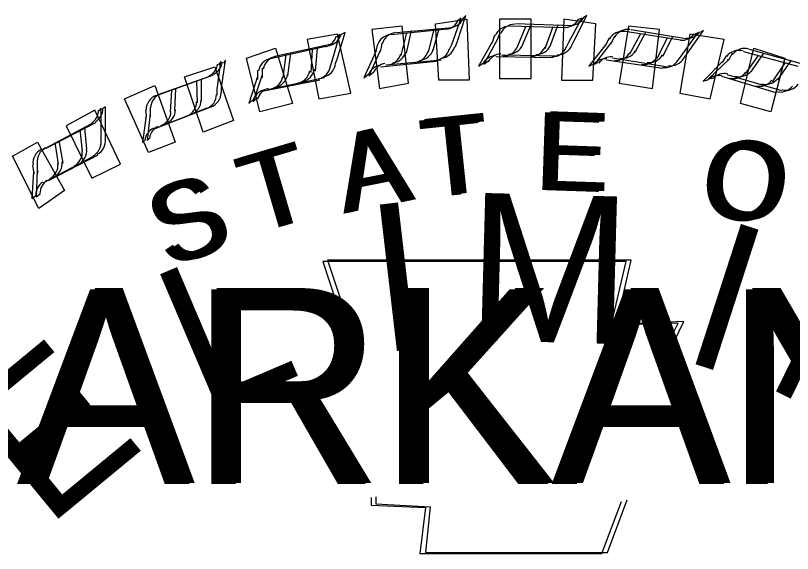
# Model space of a CAD drawing. Extents: x -40 to 1219, y 101 to 761.
# Drawn here: x 717.34 to 739.81, y 190.17 to 205.72 of the extents above; entities that cross this region are included whole.
import ezdxf

# ---------------------------------------------------------------- set-up
doc = ezdxf.new("R2010")
doc.units = 0
for name, color, linetype in [('Border 2660-Hwy18 - STAMP PRELIM', 7, 'Continuous'), ('Border 2660-Hwy18 - Stamp-ChrisC', 7, 'Continuous'), ('Stamp Charles W', 7, 'Continuous')]:
    doc.layers.add(name, color=color, linetype=linetype)

msp = doc.modelspace()

# ---------------------------------------------------------------- linework, layer by layer
at = {"layer": 'Border 2660-Hwy18 - STAMP PRELIM'}
for p, q in [((729.491, 205.475), (730.391, 205.61)), ((729.581, 203.855), (729.491, 205.475)), ((730.391, 205.61), (730.46, 203.855)), ((732.26, 205.61), (731.336, 205.61)), ((731.336, 205.61), (731.336, 203.9)), ((732.26, 203.9), (732.26, 205.61)), ((733.205, 205.61), (733.136, 203.855)), ((734.126, 205.475), (733.205, 205.61)), ((734.036, 203.855), (734.126, 205.475)), ((728.525, 205.409), (727.646, 205.319)), ((727.646, 205.319), (727.871, 203.609)), ((728.705, 203.765), (728.525, 205.409)), ((735.071, 205.409), (734.801, 203.765)), ((735.971, 205.319), (735.071, 205.409)), ((735.77, 203.609), (735.971, 205.319)), ((726.656, 205.184), (725.78, 205.025)), ((725.78, 205.025), (726.116, 203.315)), ((727.04, 203.474), (726.656, 205.184)), ((736.85, 205.184), (736.556, 203.474)), ((737.84, 205.025), (736.85, 205.184)), ((737.435, 203.315), (737.84, 205.025)), ((724.025, 204.485), (724.856, 204.779)), ((724.856, 204.779), (725.351, 203.18)), ((738.311, 203.18), (738.695, 204.779)), ((738.695, 204.779), (739.595, 204.485)), ((724.406, 202.934), (724.025, 204.485)), ((739.595, 204.485), (739.19, 202.934)), ((722.225, 203.945), (723.101, 204.239)), ((723.101, 204.239), (723.641, 202.685)), ((722.765, 202.349), (722.225, 203.945)), ((730.46, 203.855), (729.581, 203.855)), ((731.336, 203.9), (732.26, 203.9)), ((733.136, 203.855), (734.036, 203.855)), ((720.491, 203.315), (721.37, 203.699)), ((721.37, 203.699), (721.955, 202.055)), ((727.871, 203.609), (728.705, 203.765)), ((734.801, 203.765), (735.77, 203.609)), ((726.116, 203.315), (727.04, 203.474)), ((736.556, 203.474), (737.435, 203.315)), ((721.19, 201.764), (720.491, 203.315)), ((725.351, 203.18), (724.406, 202.934)), ((739.19, 202.934), (738.311, 203.18)), ((719.636, 202.979), (718.805, 202.529)), ((720.38, 201.425), (719.636, 202.979)), ((718.805, 202.529), (719.546, 201.02)), ((723.641, 202.685), (722.765, 202.349)), ((717.251, 201.65), (717.971, 202.055)), ((717.971, 202.055), (718.76, 200.66)), ((721.955, 202.055), (721.19, 201.764)), ((718.016, 200.144), (717.251, 201.65)), ((719.546, 201.02), (720.38, 201.425)), ((718.76, 200.66), (718.016, 200.144))]:
    msp.add_line(p, q, dxfattribs=at)
at = {"layer": 'Border 2660-Hwy18 - Stamp-ChrisC'}
for p, q in [((729.963, 204.883), (730.233, 205.648)), ((730.233, 205.648), (730.143, 205.579)), ((733.338, 204.928), (733.719, 205.648)), ((733.719, 205.648), (733.629, 205.603)), ((731.649, 205.423), (733.269, 205.378)), ((728.208, 205.174), (729.828, 205.333)), ((728.499, 204.568), (728.658, 205.219)), ((729.288, 204.658), (729.444, 205.288)), ((731.853, 204.793), (732.099, 205.399)), ((732.663, 204.769), (732.888, 205.399)), ((734.979, 205.264), (736.578, 205.018)), ((735.114, 204.613), (735.429, 205.198)), ((736.599, 204.544), (737.073, 205.219)), ((737.073, 205.219), (736.983, 205.174)), ((726.498, 204.409), (726.723, 205.174)), ((726.723, 205.174), (726.633, 205.108)), ((731.133, 204.973), (730.728, 204.253)), ((731.133, 204.973), (731.109, 204.904)), ((731.199, 205.153), (731.133, 204.973)), ((734.508, 205.063), (734.418, 204.883)), ((735.903, 204.478), (736.194, 205.063)), ((724.719, 204.478), (726.318, 204.838)), ((727.803, 204.859), (727.758, 204.679)), ((729.894, 204.748), (729.963, 204.883)), ((733.269, 204.793), (733.338, 204.928)), ((734.418, 204.883), (733.923, 204.253)), ((734.418, 204.883), (734.394, 204.838)), ((725.079, 203.914), (725.169, 204.589)), ((725.889, 204.073), (725.934, 204.724)), ((727.758, 204.679), (727.419, 203.914)), ((727.758, 204.679), (727.734, 204.613)), ((732.888, 204.499), (731.244, 204.523)), ((736.509, 204.433), (736.599, 204.544)), ((737.904, 204.568), (737.814, 204.409)), ((738.399, 204.679), (739.974, 204.253)), ((738.444, 204.028), (738.828, 204.568)), ((723.168, 203.578), (723.279, 204.388)), ((723.279, 204.388), (723.213, 204.298)), ((726.453, 204.253), (726.498, 204.409)), ((729.513, 204.388), (727.893, 204.229)), ((730.728, 204.253), (730.863, 204.343)), ((733.923, 204.253), (734.058, 204.319)), ((736.059, 204.184), (734.439, 204.433)), ((737.814, 204.409), (737.229, 203.824)), ((737.814, 204.409), (737.769, 204.364)), ((739.233, 203.803), (739.614, 204.364)), ((724.338, 204.139), (724.338, 203.959)), ((721.389, 203.398), (722.943, 203.959)), ((724.338, 203.959), (724.089, 203.173)), ((724.338, 203.959), (724.338, 203.869)), ((727.419, 203.914), (727.554, 204.028)), ((737.229, 203.824), (737.388, 203.869)), ((739.344, 203.488), (737.769, 203.959)), ((722.604, 203.194), (722.583, 203.824)), ((726.138, 203.848), (724.518, 203.533)), ((721.818, 202.924), (721.863, 203.554)), ((723.168, 203.419), (723.168, 203.578)), ((724.089, 203.173), (724.203, 203.284)), ((719.814, 203.038), (719.748, 202.969)), ((719.814, 202.249), (719.814, 203.038)), ((721.098, 202.993), (721.119, 202.834)), ((722.874, 203.038), (721.323, 202.429)), ((721.119, 202.834), (721.008, 202.048)), ((721.119, 202.834), (721.098, 202.744)), ((718.104, 201.823), (719.523, 202.588)), ((719.274, 201.799), (719.208, 202.429)), ((719.814, 202.093), (719.814, 202.249)), ((721.008, 202.048), (721.098, 202.138)), ((718.578, 201.418), (718.488, 202.048)), ((719.589, 201.643), (718.149, 200.878)), ((717.834, 201.394), (717.858, 201.214)), ((717.858, 201.214), (717.813, 200.428)), ((717.858, 201.214), (717.879, 201.148)), ((717.813, 200.428), (717.924, 200.518))]:
    msp.add_line(p, q, dxfattribs=at)
for points in [[(726.228, 198.604), (726.993, 196.288)], [(736.104, 196.018), (736.509, 196.828), (734.574, 196.759), (735.003, 198.604), (726.228, 198.604)], [(727.623, 191.788), (727.623, 191.563), (729.198, 191.494), (729.039, 190.168), (734.304, 190.168), (734.868, 191.674)]]:
    msp.add_lwpolyline(points, dxfattribs=at)
for centre, start, end in [((729.735, 205.759), 279.9249, 338.7128), ((733.234, 205.82), 273.4236, 332.2115), ((731.624, 204.965), 89.1628, 157.5368), ((734.895, 204.817), 81.4231, 149.797), ((726.187, 205.236), 286.2701, 345.0579), ((728.232, 204.727), 95.6641, 164.0381), ((736.606, 205.448), 265.6839, 324.4717), ((729.461, 204.873), 275.6641, 344.0381), ((731.453, 204.993), 269.1628, 337.5368), ((732.246, 204.978), 269.1628, 337.5368), ((732.862, 204.971), 269.1628, 337.5368), ((728.059, 204.735), 275.6641, 344.0381), ((728.848, 204.81), 275.6641, 344.0381), ((731.251, 204.115), 93.4236, 152.2115), ((734.729, 204.868), 261.4231, 329.797), ((735.513, 204.747), 261.4231, 329.797), ((738.263, 204.268), 73.9909, 142.3649), ((722.746, 204.372), 294.8371, 353.6249), ((724.807, 204.043), 102.0093, 170.3833), ((734.411, 204.026), 85.6839, 144.4717), ((736.122, 204.657), 261.4231, 329.797), ((725.411, 204.195), 282.0093, 350.3833), ((726.013, 204.325), 282.0093, 350.3833), ((727.958, 203.841), 99.9249, 158.7128), ((724.634, 204.033), 282.0093, 350.3833), ((737.681, 203.546), 78.2517, 137.0395), ((738.106, 204.34), 253.9909, 322.3649), ((738.867, 204.118), 253.9909, 322.3649), ((739.46, 203.95), 253.9909, 322.3649), ((721.559, 202.988), 110.5763, 178.9503), ((722.71, 203.446), 290.5763, 358.9503), ((724.633, 203.133), 106.2701, 165.0579), ((722.134, 203.228), 290.5763, 358.9503), ((719.294, 202.975), 301.9545, 0.7423), ((721.39, 202.952), 290.5763, 358.9503), ((721.523, 202.061), 114.8371, 173.6249), ((719.372, 202.051), 297.6937, 6.0677), ((718.287, 201.454), 117.6937, 186.0677), ((718.828, 201.763), 297.6937, 6.0677), ((718.124, 201.397), 297.6937, 6.0677), ((718.366, 200.53), 121.9545, 180.7423)]:
    msp.add_arc(centre, 0.444, start, end, dxfattribs=at)
at = {"layer": 'Stamp Charles W'}
for p, q in [((730.112, 204.946), (730.369, 205.719)), ((730.369, 205.719), (730.283, 205.633)), ((733.491, 204.974), (733.863, 205.719)), ((733.863, 205.719), (733.777, 205.662)), ((731.801, 205.49), (733.434, 205.433)), ((732.002, 204.86), (732.259, 205.461)), ((732.804, 204.831), (733.033, 205.461)), ((726.646, 204.459), (726.875, 205.232)), ((726.875, 205.232), (726.761, 205.175)), ((728.365, 205.232), (729.968, 205.375)), ((728.651, 204.631), (728.794, 205.29)), ((729.424, 204.717), (729.596, 205.347)), ((731.343, 205.204), (731.286, 205.032)), ((735.152, 205.318), (736.727, 205.06)), ((735.267, 204.659), (735.582, 205.261)), ((736.756, 204.602), (737.243, 205.29)), ((737.243, 205.29), (737.157, 205.232)), ((731.286, 205.032), (730.885, 204.316)), ((731.286, 205.032), (731.257, 204.974)), ((733.434, 204.86), (733.491, 204.974)), ((734.665, 205.118), (734.579, 204.946)), ((736.068, 204.545), (736.355, 205.118)), ((724.842, 204.545), (726.446, 204.889)), ((726.016, 204.115), (726.073, 204.774)), ((727.935, 204.917), (727.906, 204.745)), ((730.054, 204.803), (730.112, 204.946)), ((734.579, 204.946), (734.092, 204.316)), ((734.579, 204.946), (734.551, 204.889)), ((725.214, 203.972), (725.3, 204.631)), ((727.906, 204.745), (727.563, 203.972)), ((727.906, 204.745), (727.878, 204.659)), ((733.033, 204.545), (731.4, 204.574)), ((736.67, 204.488), (736.756, 204.602)), ((738.073, 204.631), (737.987, 204.459)), ((738.56, 204.745), (740.135, 204.316)), ((738.617, 204.087), (738.99, 204.631)), ((723.296, 203.628), (723.41, 204.43)), ((723.41, 204.43), (723.353, 204.344)), ((726.589, 204.316), (726.646, 204.459)), ((729.653, 204.43), (728.05, 204.287)), ((730.885, 204.316), (730.999, 204.402)), ((734.092, 204.316), (734.207, 204.373)), ((736.212, 204.23), (734.608, 204.488)), ((737.987, 204.459), (737.386, 203.886)), ((737.987, 204.459), (737.93, 204.43)), ((739.391, 203.858), (739.791, 204.43)), ((724.47, 204.201), (724.47, 204.001)), ((727.563, 203.972), (727.706, 204.087)), ((721.52, 203.457), (723.066, 204.001)), ((722.723, 203.256), (722.723, 203.886)), ((724.47, 204.001), (724.212, 203.228)), ((724.47, 204.001), (724.47, 203.915)), ((726.274, 203.915), (724.642, 203.571)), ((737.386, 203.886), (737.558, 203.915)), ((739.505, 203.543), (737.93, 204.001)), ((723.296, 203.485), (723.296, 203.628)), ((721.95, 202.97), (721.978, 203.6)), ((724.212, 203.228), (724.327, 203.342)), ((719.945, 203.084), (719.859, 203.027)), ((719.945, 202.311), (719.945, 203.084)), ((721.234, 203.056), (721.234, 202.884)), ((723.009, 203.084), (721.463, 202.483)), ((721.234, 202.884), (721.148, 202.111)), ((721.234, 202.884), (721.234, 202.798)), ((718.226, 201.881), (719.658, 202.626)), ((719.401, 201.853), (719.343, 202.483)), ((719.945, 202.139), (719.945, 202.311)), ((718.713, 201.452), (718.599, 202.111)), ((721.148, 202.111), (721.234, 202.197)), ((719.716, 201.681), (718.284, 200.936)), ((717.969, 201.452), (717.969, 201.251)), ((717.969, 201.251), (717.94, 200.478)), ((717.969, 201.251), (717.997, 201.194)), ((717.94, 200.478), (718.055, 200.564))]:
    msp.add_line(p, q, dxfattribs=at)
for points in [[(726.36, 198.645), (727.133, 196.326)], [(736.269, 196.039), (736.67, 196.87), (734.722, 196.784), (735.152, 198.645), (726.36, 198.645)], [(727.763, 191.801), (727.763, 191.6), (729.338, 191.514), (729.195, 190.197), (734.465, 190.197), (735.037, 191.715)]]:
    msp.add_lwpolyline(points, dxfattribs=at)
for centre, start, end in [((729.885, 205.818), 279.9249, 338.7128), ((733.391, 205.879), 273.4236, 332.2115), ((731.777, 205.022), 89.1628, 157.5368), ((728.378, 204.783), 95.6641, 164.0381), ((735.056, 204.874), 81.4231, 149.797), ((736.77, 205.506), 265.6839, 324.4717), ((726.329, 205.293), 286.2701, 345.0579), ((729.61, 204.93), 275.6641, 344.0381), ((731.606, 205.05), 269.1628, 337.5368), ((732.401, 205.035), 269.1628, 337.5368), ((733.018, 205.028), 269.1628, 337.5368), ((738.432, 204.323), 73.9909, 142.3649), ((724.946, 204.098), 102.0093, 170.3833), ((728.205, 204.792), 275.6641, 344.0381), ((728.996, 204.867), 275.6641, 344.0381), ((731.404, 204.17), 93.4236, 152.2115), ((734.571, 204.081), 85.6839, 144.4717), ((734.89, 204.925), 261.4231, 329.797), ((735.675, 204.803), 261.4231, 329.797), ((722.88, 204.428), 294.8371, 353.6249), ((726.154, 204.38), 282.0093, 350.3833), ((728.104, 203.895), 99.9249, 158.7128), ((736.286, 204.713), 261.4231, 329.797), ((725.551, 204.25), 282.0093, 350.3833), ((738.274, 204.396), 253.9909, 322.3649), ((724.773, 204.088), 282.0093, 350.3833), ((737.849, 203.6), 78.2517, 137.0395), ((739.037, 204.173), 253.9909, 322.3649), ((739.631, 204.005), 253.9909, 322.3649), ((721.691, 203.04), 110.5763, 178.9503), ((722.844, 203.499), 290.5763, 358.9503), ((724.771, 203.186), 106.2701, 165.0579), ((722.266, 203.281), 290.5763, 358.9503), ((719.42, 203.028), 301.9545, 0.7423), ((721.521, 203.004), 290.5763, 358.9503), ((721.654, 202.112), 114.8371, 173.6249), ((719.498, 202.102), 297.6937, 6.0677), ((718.411, 201.503), 117.6937, 186.0677), ((718.953, 201.813), 297.6937, 6.0677), ((718.247, 201.446), 297.6937, 6.0677), ((718.49, 200.577), 121.9545, 180.7423)]:
    msp.add_arc(centre, 0.445, start, end, dxfattribs=at)

# ---------------------------------------------------------------- texts
at = {"layer": 'Border 2660-Hwy18 - STAMP PRELIM'}
for s, rotation, p in [('M', 358.4667, (730.346, 196.34)), ('I', 6.6752, (727.85, 195.959)), ('I', 342.0495, (736.511, 195.8)), ('N', 333.841, (738.92, 195.059)), ('L', 23.0924, (722.765, 194.135)), ('E', 39.5095, (718.22, 190.874))]:
    msp.add_text(s, height=4.263, rotation=rotation, dxfattribs=at).set_placement(p)
at = {"layer": 'Border 2660-Hwy18 - Stamp-ChrisC'}
for s, height, rotation, p in [('T', 2.25, 6.0228, (729.183, 200.437)), ('E', 2.25, 358.0732, (732.333, 200.683)), ('A', 2.25, 11.2132, (726.819, 199.987)), ('O', 2.249, 350.4515, (737.034, 200.008)), ('T', 2.25, 16.4036, (724.209, 199.378)), ('S', 2.25, 21.594, (721.734, 198.388))]:
    msp.add_text(s, height=height, rotation=rotation, dxfattribs=at).set_placement(p)
msp.add_text('ARKANSAS', height=5.6249, dxfattribs=at).set_placement((717.369, 192.178))
at = {"layer": 'Stamp Charles W'}
for s, height, rotation, p in [('E', 2.255, 358.0732, (732.489, 200.707)), ('T', 2.255, 6.0228, (729.338, 200.478)), ('A', 2.255, 11.2132, (726.961, 200.02)), ('T', 2.255, 16.4036, (724.355, 199.419)), ('O', 2.254, 350.4515, (737.214, 200.049)), ('S', 2.255, 21.594, (721.892, 198.416))]:
    msp.add_text(s, height=height, rotation=rotation, dxfattribs=at).set_placement(p)
msp.add_text('ARKANSAS', height=5.6373, dxfattribs=at).set_placement((717.51, 192.202))

doc.saveas('drawing.dxf')
